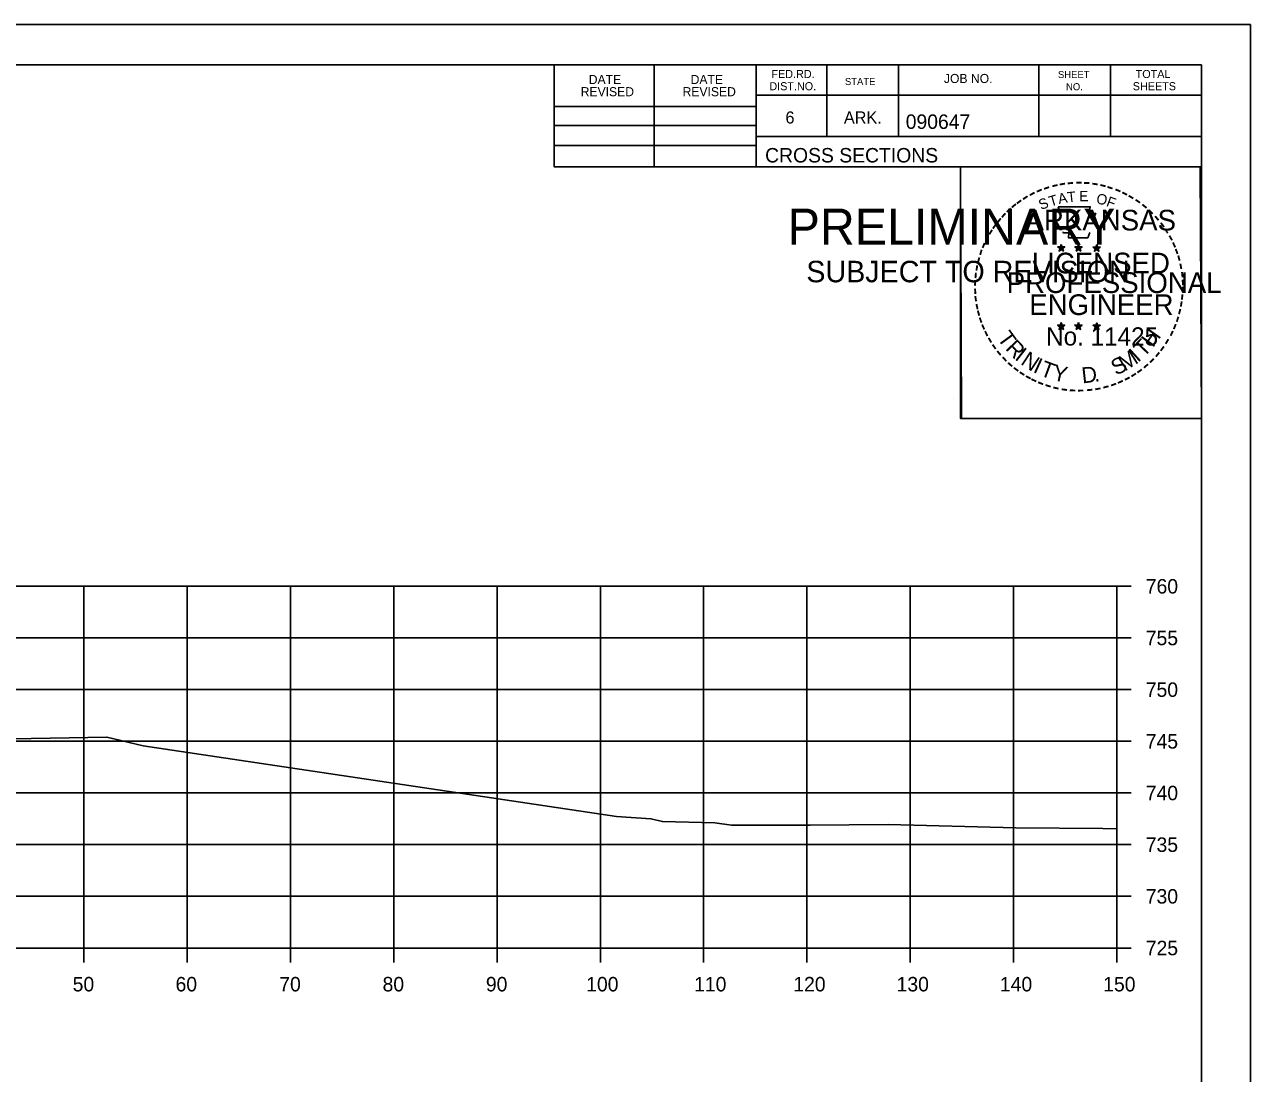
# Model space of a CAD drawing. Extents: x 1202951 to 1376887, y 378065 to 728038.
# Drawn here: x 1370161 to 1370279.6, y 380370 to 380471.5 of the extents above; entities that cross this region are included whole.
import ezdxf

# ---------------------------------------------------------------- set-up
doc = ezdxf.new("R2010")
doc.units = 0
for name, color, linetype in [('R_Axis', 7, 'Continuous'), ('R_Axis Annot', 7, 'Continuous'), ('R_Exist Surface', 7, 'Continuous'), ('R_Grid', 7, 'Continuous'), ('R_No Plot', 7, 'Continuous')]:
    doc.layers.add(name, color=color, linetype=linetype)

msp = doc.modelspace()

# ---------------------------------------------------------------- linework, layer by layer
at = {"layer": 'R_Axis'}
for p, q in [((1370266.7, 380382.18), (1370266.7, 380417.18)), ((1370268.1, 380417.18), (1370266.7, 380417.18)), ((1370268.1, 380412.18), (1370266.7, 380412.18)), ((1370268.1, 380407.18), (1370266.7, 380407.18)), ((1370268.1, 380402.18), (1370266.7, 380402.18)), ((1370268.1, 380397.18), (1370266.7, 380397.18)), ((1370268.1, 380392.18), (1370266.7, 380392.18)), ((1370268.1, 380387.18), (1370266.7, 380387.18)), ((1369966.7, 380382.18), (1370266.7, 380382.18)), ((1370166.7, 380380.78), (1370166.7, 380382.18)), ((1370176.7, 380380.78), (1370176.7, 380382.18)), ((1370186.7, 380380.78), (1370186.7, 380382.18)), ((1370196.7, 380380.78), (1370196.7, 380382.18)), ((1370206.7, 380380.78), (1370206.7, 380382.18)), ((1370216.7, 380380.78), (1370216.7, 380382.18)), ((1370226.7, 380380.78), (1370226.7, 380382.18)), ((1370236.7, 380380.78), (1370236.7, 380382.18)), ((1370246.7, 380380.78), (1370246.7, 380382.18)), ((1370256.7, 380380.78), (1370256.7, 380382.18)), ((1370266.7, 380380.78), (1370266.7, 380382.18)), ((1370268.1, 380382.18), (1370266.7, 380382.18))]:
    msp.add_line(p, q, dxfattribs=at)
at = {"layer": 'R_Exist Surface'}
msp.add_lwpolyline([(1370157.94, 380402.4), (1370168.94, 380402.59), (1370172.45, 380401.74), (1370218.25, 380394.89), (1370221.6, 380394.68), (1370222.71, 380394.41), (1370227.78, 380394.3), (1370229.39, 380394.06), (1370237, 380394.07), (1370244.55, 380394.13), (1370256.91, 380393.82), (1370265.35, 380393.74), (1370266.7, 380393.7)], dxfattribs=at)
at = {"layer": 'R_Grid'}
for p, q in [((1369966.7, 380417.18), (1370266.7, 380417.18)), ((1370166.7, 380382.18), (1370166.7, 380417.18)), ((1370176.7, 380382.18), (1370176.7, 380417.18)), ((1370186.7, 380382.18), (1370186.7, 380417.18)), ((1370196.7, 380382.18), (1370196.7, 380417.18)), ((1370206.7, 380382.18), (1370206.7, 380417.18)), ((1370216.7, 380382.18), (1370216.7, 380417.18)), ((1370226.7, 380382.18), (1370226.7, 380417.18)), ((1370236.7, 380382.18), (1370236.7, 380417.18)), ((1370246.7, 380382.18), (1370246.7, 380417.18)), ((1370256.7, 380382.18), (1370256.7, 380417.18)), ((1370266.7, 380382.18), (1370266.7, 380417.18)), ((1369966.7, 380412.18), (1370266.7, 380412.18)), ((1369966.7, 380407.18), (1370266.7, 380407.18)), ((1369966.7, 380402.18), (1370266.7, 380402.18)), ((1369966.7, 380397.18), (1370266.7, 380397.18)), ((1369966.7, 380392.18), (1370266.7, 380392.18)), ((1369966.7, 380387.18), (1370266.7, 380387.18)), ((1369966.7, 380382.18), (1370266.7, 380382.18))]:
    msp.add_line(p, q, dxfattribs=at)
at = {"layer": 'R_No Plot'}
for p, q in [((1369946.3, 380471.54), (1370279.63, 380471.54)), ((1369958.7, 380467.64), (1370274.88, 380467.64)), ((1370212.24, 380457.76), (1370212.24, 380467.64)), ((1370221.92, 380457.76), (1370221.92, 380467.64)), ((1370231.78, 380467.64), (1370231.78, 380457.76)), ((1370238.62, 380467.64), (1370238.62, 380460.7)), ((1370245.56, 380467.64), (1370245.56, 380460.7)), ((1370259.14, 380467.64), (1370259.14, 380460.7)), ((1370266.08, 380467.64), (1370266.08, 380460.7)), ((1370274.88, 380262.18), (1370274.88, 380467.64)), ((1370212.24, 380463.62), (1370231.78, 380463.62)), ((1370274.88, 380464.7), (1370231.78, 380464.7)), ((1370274.88, 380464.72), (1370274.88, 380464.72)), ((1370212.24, 380461.76), (1370231.78, 380461.76)), ((1370274.88, 380460.7), (1370231.78, 380460.7)), ((1370234.74, 380460.7), (1370274.88, 380460.7)), ((1370212.24, 380459.82), (1370231.78, 380459.82)), ((1370274.88, 380457.76), (1370212.24, 380457.76)), ((1370260.97, 380450.02), (1370261.32, 380449.91)), ((1370260.97, 380450.02), (1370261.22, 380449.97)), ((1370260.97, 380450.02), (1370261.2, 380449.9)), ((1370261.1, 380449.61), (1370261.32, 380449.91)), ((1370261.1, 380449.61), (1370261.23, 380449.86)), ((1370261.1, 380449.61), (1370261.31, 380449.83)), ((1370261.32, 380450.27), (1370261.28, 380450.02)), ((1370261.53, 380449.61), (1370261.31, 380449.83)), ((1370261.32, 380449.91), (1370261.32, 380450.27)), ((1370261.32, 380450.27), (1370261.37, 380450.02)), ((1370261.66, 380450.02), (1370261.32, 380449.91)), ((1370261.53, 380449.61), (1370261.32, 380449.91)), ((1370261.66, 380450.02), (1370261.38, 380449.97)), ((1370261.53, 380449.61), (1370261.39, 380449.9)), ((1370261.66, 380450.02), (1370261.46, 380449.92)), ((1370262.64, 380450.02), (1370262.99, 380449.91)), ((1370262.64, 380450.02), (1370262.89, 380449.97)), ((1370262.64, 380450.02), (1370262.87, 380449.9)), ((1370262.77, 380449.61), (1370262.99, 380449.91)), ((1370262.77, 380449.61), (1370262.9, 380449.86)), ((1370262.77, 380449.61), (1370262.98, 380449.83)), ((1370262.99, 380450.27), (1370262.95, 380450.02)), ((1370263.2, 380449.61), (1370262.98, 380449.83)), ((1370262.99, 380449.91), (1370262.99, 380450.27)), ((1370262.99, 380450.27), (1370263.04, 380450.02)), ((1370263.33, 380450.02), (1370262.99, 380449.91)), ((1370263.2, 380449.61), (1370262.99, 380449.91)), ((1370263.33, 380450.02), (1370263.05, 380449.97)), ((1370263.2, 380449.61), (1370263.06, 380449.9)), ((1370263.33, 380450.02), (1370263.13, 380449.92)), ((1370264.4, 380450.01), (1370264.75, 380449.9)), ((1370264.4, 380450.01), (1370264.65, 380449.96)), ((1370264.4, 380450.01), (1370264.64, 380449.89)), ((1370264.53, 380449.6), (1370264.75, 380449.9)), ((1370264.53, 380449.6), (1370264.66, 380449.84)), ((1370264.53, 380449.6), (1370264.75, 380449.82)), ((1370264.75, 380450.26), (1370264.71, 380450.01)), ((1370264.75, 380449.9), (1370264.75, 380450.26)), ((1370264.75, 380450.26), (1370264.8, 380450.01)), ((1370265.1, 380450.01), (1370264.75, 380449.9)), ((1370264.96, 380449.6), (1370264.75, 380449.9)), ((1370264.96, 380449.6), (1370264.75, 380449.81)), ((1370265.1, 380450.01), (1370264.81, 380449.96)), ((1370264.96, 380449.6), (1370264.83, 380449.89)), ((1370265.1, 380450.01), (1370264.89, 380449.91)), ((1370260.96, 380442.45), (1370261.31, 380442.34)), ((1370260.96, 380442.45), (1370261.22, 380442.4)), ((1370260.96, 380442.45), (1370261.2, 380442.32)), ((1370261.1, 380442.04), (1370261.31, 380442.34)), ((1370261.1, 380442.04), (1370261.22, 380442.28)), ((1370261.1, 380442.04), (1370261.31, 380442.26)), ((1370261.31, 380442.7), (1370261.27, 380442.45)), ((1370261.31, 380442.34), (1370261.31, 380442.7)), ((1370261.31, 380442.7), (1370261.36, 380442.45)), ((1370261.66, 380442.45), (1370261.31, 380442.34)), ((1370261.53, 380442.04), (1370261.31, 380442.34)), ((1370261.53, 380442.04), (1370261.31, 380442.25)), ((1370261.66, 380442.45), (1370261.37, 380442.4)), ((1370261.53, 380442.04), (1370261.39, 380442.33)), ((1370261.66, 380442.45), (1370261.46, 380442.34)), ((1370262.63, 380442.45), (1370262.98, 380442.34)), ((1370262.63, 380442.45), (1370262.89, 380442.4)), ((1370262.63, 380442.45), (1370262.87, 380442.32)), ((1370262.77, 380442.04), (1370262.98, 380442.34)), ((1370262.77, 380442.04), (1370262.89, 380442.28)), ((1370262.77, 380442.04), (1370262.98, 380442.26)), ((1370262.98, 380442.7), (1370262.94, 380442.45)), ((1370262.98, 380442.34), (1370262.98, 380442.7)), ((1370262.98, 380442.7), (1370263.03, 380442.45)), ((1370263.33, 380442.45), (1370262.98, 380442.34)), ((1370263.19, 380442.04), (1370262.98, 380442.34)), ((1370263.19, 380442.04), (1370262.98, 380442.25)), ((1370263.33, 380442.45), (1370263.04, 380442.4)), ((1370263.19, 380442.04), (1370263.06, 380442.33)), ((1370263.33, 380442.45), (1370263.12, 380442.34)), ((1370264.4, 380442.44), (1370264.75, 380442.33)), ((1370264.4, 380442.44), (1370264.65, 380442.39)), ((1370264.4, 380442.44), (1370264.64, 380442.31)), ((1370264.53, 380442.03), (1370264.75, 380442.33)), ((1370264.53, 380442.03), (1370264.66, 380442.27)), ((1370264.53, 380442.03), (1370264.75, 380442.25)), ((1370264.75, 380442.69), (1370264.71, 380442.44)), ((1370264.75, 380442.33), (1370264.75, 380442.69)), ((1370264.75, 380442.69), (1370264.8, 380442.44)), ((1370265.1, 380442.44), (1370264.75, 380442.33)), ((1370264.96, 380442.03), (1370264.75, 380442.33)), ((1370264.96, 380442.03), (1370264.75, 380442.24)), ((1370265.1, 380442.44), (1370264.81, 380442.39)), ((1370264.96, 380442.03), (1370264.82, 380442.32)), ((1370265.1, 380442.44), (1370264.89, 380442.33)), ((1370250.92, 380435.31), (1370250.92, 380435.31))]:
    msp.add_line(p, q, dxfattribs=at)
for points in [[(1369946.29, 380471.54), (1370279.63, 380471.54), (1370279.63, 380258.2), (1369946.29, 380258.2)], [(1370192.62, 380467.64), (1370212.24, 380467.64), (1370212.24, 380457.76), (1370228.35, 380457.76), (1370251.55, 380457.76), (1370251.55, 380433.43), (1370274.88, 380433.43), (1370274.88, 380262.18), (1369958.7, 380262.18), (1369958.7, 380467.64)], [(1370251.55, 380457.76), (1370274.76, 380457.76), (1370274.88, 380433.43), (1370251.67, 380433.43)]]:
    msp.add_lwpolyline(points, close=True, dxfattribs=at)
for points in [[(1370261.01, 380453.9), (1370261.28, 380453.07)], [(1370264.52, 380452.98), (1370264.66, 380453.26), (1370263.98, 380453.24), (1370264.12, 380453.9), (1370261.01, 380453.9)], [(1370261.5, 380451.47), (1370261.5, 380451.39), (1370262.06, 380451.37), (1370262.01, 380450.9), (1370263.88, 380450.9), (1370264.08, 380451.43)], [(1370261.32, 380450.27), (1370261.53, 380449.61), (1370260.97, 380450.02), (1370261.66, 380450.02), (1370261.1, 380449.61), (1370261.32, 380450.27)], [(1370262.99, 380450.27), (1370263.2, 380449.61), (1370262.64, 380450.02), (1370263.33, 380450.02), (1370262.77, 380449.61), (1370262.99, 380450.27)], [(1370264.75, 380450.26), (1370264.96, 380449.6), (1370264.4, 380450.01), (1370265.1, 380450.01), (1370264.53, 380449.6), (1370264.75, 380450.26)], [(1370261.31, 380442.7), (1370261.53, 380442.04), (1370260.96, 380442.45), (1370261.66, 380442.45), (1370261.1, 380442.04), (1370261.31, 380442.7)], [(1370262.98, 380442.7), (1370263.19, 380442.04), (1370262.63, 380442.45), (1370263.33, 380442.45), (1370262.77, 380442.04), (1370262.98, 380442.7)], [(1370264.75, 380442.69), (1370264.96, 380442.03), (1370264.4, 380442.44), (1370265.1, 380442.44), (1370264.53, 380442.03), (1370264.75, 380442.69)]]:
    msp.add_lwpolyline(points, dxfattribs=at)
for centre, radius in [((1370261.32, 380449.91), 0.172), ((1370261.32, 380449.91), 0.145), ((1370261.32, 380449.91), 0.116), ((1370261.32, 380449.91), 0.0991), ((1370261.32, 380449.91), 0.0747), ((1370261.32, 380449.91), 0.0495), ((1370261.32, 380449.91), 0.0296), ((1370262.99, 380449.91), 0.172), ((1370262.99, 380449.91), 0.145), ((1370262.99, 380449.91), 0.116), ((1370262.99, 380449.91), 0.0991), ((1370262.99, 380449.91), 0.0747), ((1370262.99, 380449.91), 0.0495), ((1370262.99, 380449.91), 0.0296), ((1370264.75, 380449.9), 0.172), ((1370264.75, 380449.9), 0.145), ((1370264.75, 380449.9), 0.116), ((1370264.75, 380449.9), 0.0991), ((1370264.75, 380449.9), 0.0747), ((1370264.75, 380449.9), 0.0495), ((1370264.75, 380449.9), 0.0296), ((1370261.31, 380442.34), 0.172), ((1370261.31, 380442.34), 0.145), ((1370261.31, 380442.34), 0.116), ((1370261.31, 380442.34), 0.0991), ((1370261.31, 380442.34), 0.0747), ((1370261.31, 380442.34), 0.0495), ((1370261.31, 380442.34), 0.0296), ((1370262.98, 380442.34), 0.172), ((1370262.98, 380442.34), 0.145), ((1370262.98, 380442.34), 0.116), ((1370262.98, 380442.34), 0.0991), ((1370262.98, 380442.34), 0.0747), ((1370262.98, 380442.34), 0.0495), ((1370262.98, 380442.34), 0.0296), ((1370264.75, 380442.33), 0.172), ((1370264.75, 380442.33), 0.145), ((1370264.75, 380442.33), 0.116), ((1370264.75, 380442.33), 0.0991), ((1370264.75, 380442.33), 0.0747), ((1370264.75, 380442.33), 0.0495), ((1370264.75, 380442.33), 0.0296)]:
    msp.add_circle(centre, radius, dxfattribs=at)

# ---------------------------------------------------------------- texts
at = {"layer": 'R_Axis Annot'}
for s, p in [('760', (1370269.5, 380416.48)), ('755', (1370269.5, 380411.48)), ('750', (1370269.5, 380406.48)), ('745', (1370269.5, 380401.48)), ('740', (1370269.5, 380396.48)), ('735', (1370269.5, 380391.48)), ('730', (1370269.5, 380386.48)), ('725', (1370269.5, 380381.48)), ('50', (1370165.62, 380377.98)), ('60', (1370175.58, 380377.98)), ('70', (1370185.62, 380377.98)), ('80', (1370195.62, 380377.98)), ('90', (1370205.62, 380377.98)), ('100', (1370215.33, 380377.98)), ('110', (1370225.78, 380377.98)), ('120', (1370235.38, 380377.98)), ('130', (1370245.38, 380377.98)), ('140', (1370255.38, 380377.98)), ('150', (1370265.38, 380377.98))]:
    msp.add_text(s, height=1.4, dxfattribs=at).set_placement(p)
at = {"layer": 'R_No Plot'}
for s, height, rotation, p in [('DATE', 0.879, 360, (1370215.58, 380465.78)), ('DATE', 0.879, 360, (1370225.44, 380465.78)), ('DIST.NO.', 0.782, 360, (1370233.06, 380465.18)), ('FED.RD.', 0.782, 360, (1370233.26, 380466.36)), ('STATE', 0.684, 360, (1370240.38, 380465.68)), ('JOB NO.', 0.879, 360, (1370249.96, 380465.88)), ('SHEET', 0.684, 360, (1370261, 380466.36)), ('SHEETS', 0.782, 360, (1370268.24, 380465.18)), ('TOTAL', 0.782, 360, (1370268.52, 380466.36)), ('REVISED', 0.879, 360, (1370214.8, 380464.6)), ('REVISED', 0.879, 360, (1370224.66, 380464.6)), ('NO.', 0.684, 360, (1370261.78, 380465.18)), ('6', 1.17, 360, (1370234.62, 380461.96)), ('ARK.', 1.172, 360, (1370240.28, 380461.96)), ('090647', 1.4, 360, (1370246.26, 380461.44)), ('CROSS SECTIONS', 1.4, 360, (1370232.65, 380458.19)), ('-', 1.6, 28.7918, (1370258.49, 380454.44)), ('-', 1.6, 24.3072, (1370259.12, 380454.76)), ('-', 1.6, 19.1761, (1370259.76, 380455.02)), ('-', 1.6, 13.6301, (1370260.51, 380455.27)), ('-', 1.6, 10.2193, (1370261.18, 380455.43)), ('T', 1, 6.0228, (1370261.95, 380454.32)), ('-', 1.6, 5.8968, (1370261.91, 380455.54)), ('-', 1.6, 0.1862, (1370262.68, 380455.61)), ('E', 1, 0.8323, (1370263.06, 380454.43)), ('-', 1.6, 357.743, (1370263.41, 380455.6)), ('-', 1.6, 352.1617, (1370264.15, 380455.54)), ('-', 1.6, 347.2049, (1370264.87, 380455.43)), ('-', 1.6, 342.3362, (1370265.51, 380455.27)), ('-', 1.6, 337.8551, (1370266.24, 380455.05)), ('-', 1.6, 334.1211, (1370266.87, 380454.78)), ('-', 1.6, 38.9507, (1370256.84, 380453.3)), ('-', 1.6, 36.2317, (1370257.31, 380453.67)), ('-', 1.6, 34.0636, (1370257.89, 380454.07)), ('S', 1, 21.594, (1370259.36, 380453.58)), ('T', 1, 16.4036, (1370260.28, 380453.91)), ('A', 1, 11.2132, (1370261.1, 380454.16)), ('O', 1, 350.4515, (1370264.66, 380454.22)), ('F', 1, 340.0707, (1370265.61, 380454)), ('-', 1.6, 329.6409, (1370267.45, 380454.49)), ('-', 1.6, 325.8627, (1370268.09, 380454.13)), ('-', 1.6, 320.5297, (1370268.7, 380453.71)), ('PRELIMINARY', 3.5, 360, (1370234.83, 380450.23)), ('-', 1.6, 48.423, (1370255.96, 380452.4)), ('-', 1.6, 42.9622, (1370256.4, 380452.88)), ('ARKANSAS', 2, 360, (1370257.86, 380451.61)), ('-', 1.6, 315.5786, (1370269.3, 380453.22)), ('-', 1.6, 309.8797, (1370269.87, 380452.67)), ('DWB', 0.01, 360, (1370235.58, 380452.08)), ('-', 1.6, 54.2325, (1370255.14, 380451.35)), ('-', 1.6, 50.6142, (1370255.55, 380451.91)), ('-', 1.6, 306.6522, (1370270.4, 380452.07)), ('-', 1.4, 303.6753, (1370270.88, 380451.5)), ('-', 1.6, 62.8713, (1370254.5, 380450.21)), ('-', 1.6, 58.0706, (1370254.82, 380450.82)), ('-', 1.6, 299.6684, (1370271.2, 380450.89)), ('-', 1.6, 72.3945, (1370254.02, 380448.97)), ('-', 1.6, 67.7743, (1370254.24, 380449.6)), ('LICENSED', 2, 360, (1370258.46, 380447.46)), ('DWB', 0.01, 360, (1370261.3, 380449.9)), ('DWB', 0.01, 360, (1370262.97, 380449.9)), ('DWB', 0.01, 360, (1370264.74, 380449.89)), ('-', 1.6, 294.6628, (1370271.53, 380450.28)), ('-', 1.6, 290.5728, (1370271.78, 380449.7)), ('SUBJECT TO REVISION', 2.0751, 360, (1370236.64, 380446.6)), ('-', 1.6, 81.2013, (1370253.7, 380447.54)), ('-', 1.6, 75.461, (1370253.83, 380448.25)), ('-', 1.6, 285.1233, (1370272.02, 380449.12)), ('-', 1.6, 280.5493, (1370272.22, 380448.38)), ('-', 1.6, 85.1863, (1370253.62, 380446.85)), ('PROFESSIONAL', 2, 360, (1370256.03, 380445.56)), ('-', 1.6, 276.5962, (1370272.38, 380447.61)), ('-', 1.6, 94.1959, (1370253.63, 380445.42)), ('-', 1.6, 89.0622, (1370253.59, 380446.15)), ('-', 1.6, 274.3301, (1370272.44, 380446.89)), ('-', 1.6, 269.9407, (1370272.47, 380446.26)), ('-', 1.6, 98.9479, (1370253.7, 380444.75)), ('ENGINEER', 2, 360, (1370258.22, 380443.43)), ('-', 1.6, 260.9953, (1370272.38, 380444.94)), ('-', 1.6, 263.5172, (1370272.45, 380445.59)), ('-', 1.6, 101.7149, (1370253.84, 380444.02)), ('-', 1.6, 105.4578, (1370254, 380443.43)), ('-', 1.6, 255.7626, (1370272.27, 380444.26)), ('-', 1.6, 109.0874, (1370254.21, 380442.8)), ('-', 1.6, 114.0643, (1370254.47, 380442.2)), ('No. 11425', 1.757, 360, (1370259.85, 380440.48)), ('DWB', 0.01, 360, (1370261.3, 380442.33)), ('DWB', 0.01, 360, (1370262.97, 380442.33)), ('DWB', 0.01, 360, (1370264.74, 380442.32)), ('-', 1.6, 247.8887, (1370271.87, 380442.87)), ('-', 1.6, 252.8681, (1370272.09, 380443.54)), ('-', 1.6, 115.7289, (1370254.77, 380441.58)), ('-', 1.6, 120.4471, (1370255.13, 380441)), ('T', 1.54, 306.0406, (1370255.07, 380441.17)), ('R', 1.54, 314.005, (1370255.83, 380440.13)), ('T', 1.54, 46.6444, (1370269.3, 380439.27)), ('H', 1.54, 54.6088, (1370270.19, 380440.21)), ('-', 1.6, 239.0712, (1370271.21, 380441.49)), ('-', 1.6, 244.6197, (1370271.61, 380442.24)), ('-', 1.6, 125.8934, (1370255.53, 380440.43)), ('-', 1.6, 130.7181, (1370255.99, 380439.88)), ('I', 1.54, 321.9694, (1370256.73, 380439.19)), ('N', 1.54, 326.5002, (1370257.3, 380438.72)), ('M', 1.54, 32.6563, (1370267.46, 380437.94)), ('I', 1.54, 42.1136, (1370268.74, 380438.79)), ('-', 1.6, 233.8452, (1370270.81, 380440.83)), ('-', 1.6, 134.2238, (1370256.51, 380439.34)), ('-', 1.6, 138.9338, (1370257.04, 380438.87)), ('I', 1.54, 335.3603, (1370258.51, 380437.94)), ('T', 1.54, 339.8912, (1370259.17, 380437.61)), ('S', 1.54, 26.9312, (1370266.62, 380437.54)), ('-', 1.6, 221.0851, (1370269.38, 380439.2)), ('-', 1.6, 225.7653, (1370269.9, 380439.7)), ('-', 1.6, 231.2538, (1370270.38, 380440.27)), ('-', 1.6, 144.6463, (1370257.59, 380438.47)), ('-', 1.6, 148.0898, (1370258.15, 380438.1)), ('-', 1.6, 151.5704, (1370258.73, 380437.77)), ('Y', 1.54, 347.8556, (1370260.39, 380437.16)), ('D', 1.54, 6.3969, (1370263.37, 380436.81)), ('-', 1.6, 212.2491, (1370268.3, 380438.34)), ('-', 1.6, 215.7363, (1370268.83, 380438.72)), ('-', 1.6, 154.6002, (1370259.25, 380437.52)), ('-', 1.6, 158.5612, (1370259.88, 380437.27)), ('-', 1.6, 162.7983, (1370260.57, 380437.06)), ('-', 1.6, 167.5555, (1370261.28, 380436.89)), ('-', 1.6, 173.1155, (1370262.05, 380436.78)), ('-', 1.6, 191.2858, (1370265.09, 380436.96)), ('.', 1.54, 13.7642, (1370264.56, 380436.93)), ('-', 1.6, 195.4743, (1370265.82, 380437.16)), ('-', 1.6, 200.7184, (1370266.5, 380437.4)), ('-', 1.6, 204.2516, (1370267.11, 380437.67)), ('-', 1.6, 207.3568, (1370267.74, 380437.99)), ('-', 1.6, 176.5183, (1370262.8, 380436.73)), ('-', 1.6, 181.5918, (1370263.54, 380436.75)), ('-', 1.6, 185.8167, (1370264.35, 380436.83))]:
    msp.add_text(s, height=height, rotation=rotation, dxfattribs=at).set_placement(p)

doc.saveas('drawing.dxf')
